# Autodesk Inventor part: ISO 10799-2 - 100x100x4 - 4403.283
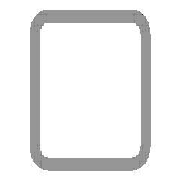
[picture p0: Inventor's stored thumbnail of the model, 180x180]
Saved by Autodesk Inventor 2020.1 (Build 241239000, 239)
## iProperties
Created: 2019-10
Part Number: ISO 10799-2 - 100x100x4 - 4403.283
Material: Stainless Steel
Description: Structural steels - Cold-formed, welded, structural hollow sections
Document SubType Name: Modeling
Standard: ISO
Designer: Synergysoft Dell02
Standard Revision: First edition 2011-09-15
Standards Organization: ISO
Language: en-US
Size Designation: 100x100x4
Categories: <MemberInstance><Categories><Category DisplayName="Structural Shapes" InternalName="089c4875-fa83-4c05-b084-43b9cc11f5ed" Mnemonic="GRDR"><CategoryParameter Dis
Stock Number: 100x100x4
Density: 8 g/cm^3
Appearance: Semi-Polished
_CCFamilyMember: 43
_CCFamilyDisplayName: ISO 10799-2 (Square) - Structural steels - Cold-formed, welded, structural hollow sections
_FrameMemberDoc: Frame Member File
_Version: 15.0.0
_GetPNFromCC: 1
G_L: 4403.283 mm
G_W: 100.000 mm
G_H: 100.000 mm
+F0EB09D6-E95E-4F0D-A0A9-255925CD8DEC+CUTDETAIL1: Miter 45.00 deg
+B4E8C4BE-60B8-4314-8C74-2DD17A406012+CUTDETAIL2: Miter 22.50 deg
IsCustomPart: 1
Author: Synergysoft Dell02
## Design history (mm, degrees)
node "Start Plane"
node "End Plane"
sketch "Sketch"
  geometry: L1 (-50, -42)-(-50, 42); L2 (-42, 50)-(42, 50); L3 (50, 42)-(50, -42); L4 (42, -50)-(-42, -50); L5 (-42, 46)-(42, 46); L6 (46, 42)-(46, -42); L7 (42, -46)-(-42, -46); L8 (-46, -42)-(-46, 42); L9 (0, 72.32)-(0, -72.32) reference; L10 (-72.32, 0)-(72.32, 0) reference; A1 r 8 centre (-42, -42) between (-50, -42) and (-42, -50); A2 r 8 centre (42, 42) between (50, 42) and (42, 50); A3 r 8 centre (-42, 42) between (-42, 50) and (-50, 42); A4 r 8 centre (42, -42) between (42, -50) and (50, -42); A5 r 4 centre (-42, 42) between (-42, 46) and (-46, 42); A6 r 4 centre (42, 42) between (46, 42) and (42, 46); A7 r 4 centre (42, -42) between (42, -46) and (46, -42); A8 r 4 centre (-42, -42) between (-46, -42) and (-42, -46)
  constraints: 16 end point, 16 point on circle, 8 centre point, 8 tangent, 4 parallel, 3 equal radius, 2 perpendicular, 7 other
  dimensions: "d7" = 8 radius of A1 (= G_IR); "d9" = 100 distance between parallel lines of L1 L3 (= G_W); "d11" = 100 distance between parallel lines of L2 L4 (= G_H); "d12" = 4 distance between parallel lines of L3 L6 (= G_T); "d15" = 50 distance between parallel lines of L9 L3 (= 0.5 x d9); "d16" = 50 distance between parallel lines of L2 L10 (= 0.5 x d11)
extrude "Body" new body sketch "Sketch" stored distance "d3" = 4403.28302 (= G_L); taper "d4" = 0 deg
node "Driven Length"
  sketch "Sketch3"
    geometry: L1 (0, 0)-(10, 0) reference
    constraints: 2 end point, 1 horizontal
  workplane "Work Plane3"
  sketch "Sketch4"
    geometry: L1 (-2, -46.464)-(12, -46.464) reference; L2 (-2, 4356.819)-(12, 4356.819) reference
    dimensions: "d18" = 4403.28302 distance between parallel lines of L1 L2 (derived)
workplane "Work Plane4"
split "Split1"
workplane "Work Plane5"
split "Split2"
body "Solid1"
other parameters: "G_W" = 100 [user parameter; used in 1 equation term], "G_H" = 100 [user parameter; used in 1 equation term], "G_T" = 4 [user parameter; used in 1 equation term], "G_IR" = 8 [user parameter; used in 1 equation term], "G_L" = 4403.28302 (= d18) [user parameter; used in 1 equation term], "G_OFFSET_START" = 46.46447 [user parameter; used in 1 equation term], "G_OFFSET_END" = 114.17786 [user parameter; used in 1 equation term], "d13" = -46.46447 (= -G_OFFSET_START), "d14" = 4356.81855 (= G_OFFSET_END + B_L), "B_L" = 4242.64069 [user parameter; used in 1 equation term], "d17" = 90 deg, "MAS" = 1.17 [user parameter]
